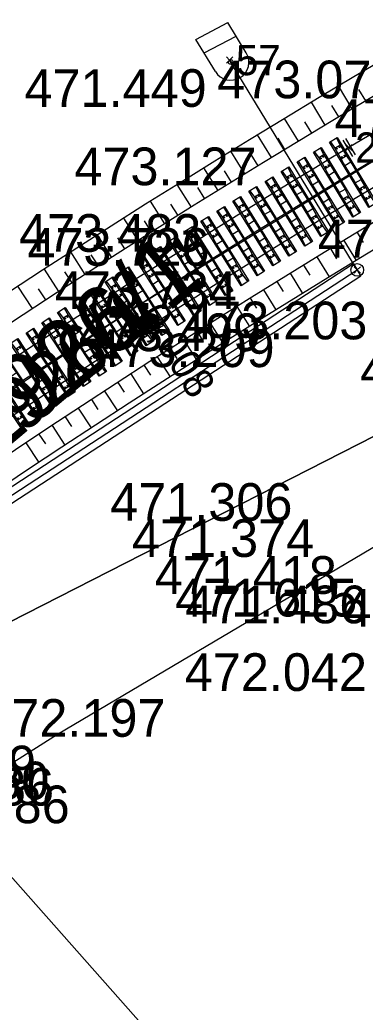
# Model space of a CAD drawing. Extents: x -758836 to -757729, y -1175316 to -1174366.
# Drawn here: x -758366.97 to -758355.97, y -1174833.52 to -1174801.92 of the extents above; entities that cross this region are included whole.
import ezdxf

# ---------------------------------------------------------------- set-up
doc = ezdxf.new("R2010")
doc.units = 0
for name, color, linetype in [('_NOR-body-stávající osa', 7, 'Continuous'), ('_NOR-návrh silná', 7, 'Continuous'), ('_NOR-návrh tenká', 7, 'Continuous'), ('_NOR-osa', 7, 'Continuous'), ('_NOR-posuny', 7, 'Continuous'), ('_NOR-pražce', 7, 'Continuous'), ('_NOR-svahy', 7, 'Continuous'), ('_vytyčený bod', 7, 'Continuous'), ('G_Obvod stavby', 7, 'Continuous'), ('Hranice parcel', 7, 'Continuous'), ('Parcelní čísla', 7, 'Continuous'), ('Vnitřní kresba', 7, 'Continuous'), ('Vrstva 1', 7, 'Continuous'), ('Vrstva 61', 7, 'Continuous')]:
    doc.layers.add(name, color=color, linetype=linetype)

# ---------------------------------------------------------------- blocks, each defined once
blk = doc.blocks.new('půdorys-SB8')
at = {"layer": '_NOR-pražce'}
for p, q in [((-1.21, 0.109), (-0.96, 0.095)), ((-0.96, 0.095), (-0.56, 0.099)), ((-0.96, 0.095), (-0.96, -0.095)), ((-0.56, 0.099), (-0.32, 0.109)), ((-0.56, 0.099), (-0.56, -0.1)), ((-0.32, 0.109), (0.32, 0.109)), ((-0.32, 0.109), (-0.32, -0.11)), ((0.56, 0.099), (0.32, 0.109)), ((0.32, -0.11), (0.32, 0.109)), ((0.96, 0.095), (0.56, 0.099)), ((0.56, 0.099), (0.56, -0.1)), ((1.21, 0.109), (0.96, 0.095)), ((0.96, 0.095), (0.96, -0.095)), ((-1.21, -0.11), (-0.96, -0.095)), ((-0.96, -0.095), (-0.56, -0.1)), ((-0.56, -0.1), (-0.32, -0.11)), ((-0.32, -0.11), (0.32, -0.11)), ((0.56, -0.1), (0.32, -0.11)), ((0.96, -0.095), (0.56, -0.1)), ((1.21, -0.11), (0.96, -0.095))]:
    blk.add_line(p, q, dxfattribs=at)
blk.add_lwpolyline([(-1.21, 0.142), (1.21, 0.142), (1.21, -0.142), (-1.21, -0.142)], close=True, dxfattribs=at)
for centre in [(-0.916, 0.048), (-0.604, 0.048), (0.604, 0.048), (0.916, 0.048), (-0.916, -0.048), (-0.604, -0.048), (0.604, -0.048), (0.916, -0.048)]:
    blk.add_circle(centre, 0.015, dxfattribs=at)
blk = doc.blocks.new('POINT_DISPLAY')
for p, q in [((-0.175, -0.175), (0.175, 0.175)), ((-0.175, 0.175), (0.175, -0.175))]:
    blk.add_line(p, q)

msp = doc.modelspace()

# ---------------------------------------------------------------- linework, layer by layer
at = {"layer": '_NOR-návrh silná'}
for p, q in [((-758356.686, -1174805.753), (-758356.377, -1174806.268)), ((-758356.6, -1174805.702), (-758356.291, -1174806.216))]:
    msp.add_line(p, q, dxfattribs=at)
at = {"layer": '_NOR-návrh tenká'}
for p, q in [((-758361.359, -1174802.548), (-758360.342, -1174802.008)), ((-758359.758, -1174802.968), (-758360.342, -1174802.008)), ((-758360.74, -1174803.566), (-758361.359, -1174802.548)), ((-758361.099, -1174802.976), (-758360.082, -1174802.436)), ((-758356.223, -1174809.884), (-758360.288, -1174803.203)), ((-758356.34, -1174809.692), (-758371.395, -1174819.503)), ((-758356.34, -1174809.692), (-758356.106, -1174810.077)), ((-758371.266, -1174819.688), (-758356.223, -1174809.884)), ((-758356.106, -1174810.077), (-758371.14, -1174819.874))]:
    msp.add_line(p, q, dxfattribs=at)
for centre, radius in [((-758360.249, -1174803.267), 0.075), ((-758356.223, -1174809.884), 0.2)]:
    msp.add_circle(centre, radius, dxfattribs=at)
for centre, radius, start, end in [((-758205.34, -1175057.864), 295.6, 97.09776, 129.28488), ((-758205.34, -1175057.864), 294.75, 97.0979, 129.28474), ((-758205.34, -1175057.864), 293.75, 97.09807, 120.96729), ((-758205.34, -1175057.864), 291.3, 97.09848, 129.28417), ((-758205.34, -1175057.864), 290.55, 97.09861, 129.28404), ((-758360.249, -1174803.267), 0.575, 211.3183, 31.3183), ((-758205.34, -1175057.864), 293.75, 120.96729, 129.28457), ((-758205.34, -1175057.864), 292.25, 120.96729, 129.28432)]:
    msp.add_arc(centre, radius, start, end, dxfattribs=at)
at = {"layer": '_NOR-osa'}
msp.add_arc((-758205.34, -1175057.864), 293, 97.09819, 129.28445, dxfattribs=at)
at = {"layer": '_NOR-svahy'}
for points in [[(-758356.383, -1174804.756), (-758356.819, -1174804.027)], [(-758355.954, -1174804.501), (-758356.171, -1174804.135)], [(-758357.241, -1174805.27), (-758357.679, -1174804.542)], [(-758356.812, -1174805.013), (-758357.031, -1174804.648)], [(-758358.097, -1174805.787), (-758358.538, -1174805.06)], [(-758357.669, -1174805.528), (-758357.889, -1174805.165)], [(-758358.952, -1174806.307), (-758359.395, -1174805.581)], [(-758358.525, -1174806.047), (-758358.745, -1174805.684)], [(-758359.804, -1174806.829), (-758360.25, -1174806.106)], [(-758359.378, -1174806.568), (-758359.6, -1174806.205)], [(-758360.655, -1174807.355), (-758361.103, -1174806.633)], [(-758360.23, -1174807.092), (-758360.453, -1174806.73)], [(-758361.504, -1174807.883), (-758361.954, -1174807.162)], [(-758361.08, -1174807.619), (-758361.304, -1174807.258)], [(-758362.351, -1174808.415), (-758362.804, -1174807.695)], [(-758361.928, -1174808.149), (-758362.154, -1174807.789)], [(-758363.197, -1174808.949), (-758363.652, -1174808.231)], [(-758362.774, -1174808.681), (-758363.001, -1174808.322)], [(-758364.04, -1174809.486), (-758364.498, -1174808.769)], [(-758363.619, -1174809.217), (-758363.847, -1174808.858)], [(-758356.225, -1174808.687), (-758356.031, -1174809.008)], [(-758357.08, -1174809.206), (-758356.884, -1174809.526)], [(-758356.653, -1174808.946), (-758356.263, -1174809.587)], [(-758364.882, -1174810.026), (-758365.342, -1174809.311)], [(-758364.461, -1174809.755), (-758364.691, -1174809.398)], [(-758357.506, -1174809.467), (-758357.114, -1174810.107)], [(-758365.722, -1174810.568), (-758366.184, -1174809.855)], [(-758357.932, -1174809.729), (-758357.736, -1174810.048)], [(-758365.302, -1174810.297), (-758365.533, -1174809.94)], [(-758358.358, -1174809.991), (-758357.964, -1174810.629)], [(-758366.56, -1174811.114), (-758367.025, -1174810.402)], [(-758366.141, -1174810.841), (-758366.373, -1174810.485)], [(-758358.783, -1174810.254), (-758358.586, -1174810.573)], [(-758359.632, -1174810.782), (-758359.434, -1174811.1)], [(-758359.208, -1174810.518), (-758358.812, -1174811.154)], [(-758360.056, -1174811.047), (-758359.658, -1174811.683)], [(-758360.48, -1174811.313), (-758360.28, -1174811.631)], [(-758360.903, -1174811.58), (-758360.502, -1174812.214)], [(-758361.325, -1174811.847), (-758361.124, -1174812.164)], [(-758362.169, -1174812.384), (-758361.967, -1174812.7)], [(-758361.747, -1174812.115), (-758361.345, -1174812.748)], [(-758362.59, -1174812.654), (-758362.185, -1174813.285)], [(-758363.011, -1174812.924), (-758362.808, -1174813.239)], [(-758363.431, -1174813.195), (-758363.024, -1174813.825)], [(-758363.85, -1174813.467), (-758363.646, -1174813.781)], [(-758364.27, -1174813.739), (-758363.861, -1174814.368)], [(-758365.107, -1174814.286), (-758364.696, -1174814.913)], [(-758364.689, -1174814.012), (-758364.483, -1174814.326)], [(-758365.525, -1174814.561), (-758365.319, -1174814.874)], [(-758365.942, -1174814.836), (-758365.529, -1174815.462)], [(-758366.359, -1174815.112), (-758366.152, -1174815.425)], [(-758366.775, -1174815.389), (-758366.36, -1174816.013)]]:
    msp.add_lwpolyline(points, dxfattribs=at)
at = {"layer": '_vytyčený bod'}
for p, q in [((-758360.288, -1174803.203), (-758360.388, -1174803.103)), ((-758360.288, -1174803.203), (-758360.388, -1174803.303)), ((-758360.288, -1174803.203), (-758360.188, -1174803.103)), ((-758360.288, -1174803.203), (-758360.188, -1174803.303)), ((-758356.489, -1174805.985), (-758356.589, -1174805.885)), ((-758356.489, -1174805.985), (-758356.589, -1174806.085)), ((-758356.489, -1174805.985), (-758356.389, -1174805.885)), ((-758356.489, -1174805.985), (-758356.389, -1174806.085)), ((-758356.223, -1174809.884), (-758356.323, -1174809.784)), ((-758356.223, -1174809.884), (-758356.123, -1174809.784)), ((-758356.223, -1174809.884), (-758356.323, -1174809.984)), ((-758356.223, -1174809.884), (-758356.123, -1174809.984))]:
    msp.add_line(p, q, dxfattribs=at)
at = {"layer": 'G_Obvod stavby'}
msp.add_lwpolyline([(-758392.72, -1174840.756), (-758391.23, -1174838.56), (-758368.37, -1174821.64), (-758340.31, -1174807.33), (-758320.27, -1174796.89), (-758301, -1174790.21), (-758267.96, -1174782.93), (-758224.96, -1174775.27), (-758184.87, -1174772.83), (-758142.71, -1174770.26), (-758089.84, -1174768.68), (-758106.02, -1174731.44), (-758149.09, -1174725.67), (-758199.62, -1174726.6), (-758225.76, -1174732.36), (-758252.17, -1174738.18), (-758254.97, -1174739.34), (-758266.58, -1174744.16), (-758279.45, -1174749.49), (-758302.42, -1174759.02), (-758331.68, -1174770.24), (-758367.17, -1174799.81), (-758405.64, -1174832.2)], dxfattribs=at)
at = {"layer": 'Hranice parcel'}
for points in [[(-758340.31, -1174807.33), (-758368.37, -1174821.64), (-758391.23, -1174838.56)], [(-758352.89, -1174817.05), (-758365.77, -1174824.68), (-758369.29, -1174826.9), (-758373.7, -1174830.81), (-758376.95, -1174833.7), (-758377.89, -1174834.53), (-758384.91, -1174840.91)]]:
    msp.add_lwpolyline(points, dxfattribs=at)
at = {"layer": 'Vnitřní kresba'}
msp.add_line((-758369.29, -1174826.9), (-758358.97, -1174838.54), dxfattribs=at)
at = {"layer": 'Vrstva 1'}
msp.add_lwpolyline([(-758443.817, -1174881.252), (-758441.673, -1174879.1), (-758423.412, -1174860.854), (-758412.446, -1174850.23), (-758405.322, -1174843.614), (-758399.028, -1174837.996), (-758392.64, -1174832.554), (-758380.106, -1174822.693), (-758371.773, -1174816.721), (-758363.37, -1174811.125), (-758354.46, -1174805.649), (-758345.526, -1174800.592), (-758336.614, -1174795.909), (-758327.338, -1174791.462), (-758317.813, -1174787.314), (-758307.666, -1174783.315), (-758298.059, -1174779.921), (-758285.017, -1174775.914), (-758275.047, -1174773.289)], dxfattribs=at)

# ---------------------------------------------------------------- block references
at = {"layer": '_NOR-body-stávající osa'}
msp.add_blockref('POINT_DISPLAY', (-758363.37, -1174811.125), dxfattribs=at)
at = {"layer": '_NOR-pražce'}
for p, rotation in [((-758356.359, -1174806.782), -58.974233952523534), ((-758356.872, -1174807.091), -58.85720429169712), ((-758357.383, -1174807.401), -58.74017459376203), ((-758357.895, -1174807.712), -58.623144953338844), ((-758358.405, -1174808.024), -58.506115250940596), ((-758358.915, -1174808.337), -58.38908558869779), ((-758359.425, -1174808.652), -58.27205592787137), ((-758359.933, -1174808.967), -58.155026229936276), ((-758360.441, -1174809.283), -58.03799658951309), ((-758360.949, -1174809.6), -57.920966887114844), ((-758361.456, -1174809.919), -57.80393722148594), ((-758361.962, -1174810.238), -57.6869075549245), ((-758362.467, -1174810.559), -57.56987785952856), ((-758362.972, -1174810.88), -57.45284819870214), ((-758363.476, -1174811.203), -57.33581850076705), ((-758363.98, -1174811.526), -57.218788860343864), ((-758364.483, -1174811.851), -57.101759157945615), ((-758364.985, -1174812.176), -56.98472949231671), ((-758365.486, -1174812.503), -56.86769982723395), ((-758365.987, -1174812.83), -56.75067012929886), ((-758366.487, -1174813.159), -56.63364048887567), ((-758366.987, -1174813.489), -56.51661078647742), ((-758367.485, -1174813.819), -56.399581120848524)]:
    msp.add_blockref('půdorys-SB8', p, dxfattribs=dict(at, rotation=rotation))

# ---------------------------------------------------------------- texts
at = {"layer": '_NOR-posuny'}
msp.add_text('0,008', height=0.9599, rotation=302.6385, dxfattribs=at).set_placement((-758363.231, -1174811.342))
at = {"layer": '_vytyčený bod'}
for s, height, p in [('57', 0.9599, (-758360.088, -1174803.683)), ('57', 0.9596, (-758360.088, -1174803.683)), ('24', 0.9599, (-758356.289, -1174806.465)), ('24', 0.9596, (-758356.289, -1174806.465))]:
    msp.add_text(s, height=height, dxfattribs=at).set_placement(p)
at = {"layer": 'Parcelní čísla'}
for height in [2.1751, 1.7]:
    msp.add_text('2926/1', height=height, rotation=40, dxfattribs=at).set_placement((-758367.845, -1174815.948))
at = {"layer": 'Vrstva 61'}
for s, p in [('473.071', (-758360.68, -1174804.418)), ('471.449', (-758366.817, -1174804.692)), ('473.628', (-758356.945, -1174805.649)), ('473.127', (-758365.23, -1174807.186)), ('473.483', (-758366.991, -1174809.307)), ('473.157', (-758357.48, -1174809.488)), ('473.726', (-758366.727, -1174809.753)), ('473.734', (-758365.855, -1174811.125)), ('473.203', (-758361.702, -1174812.093)), ('473.499', (-758365.087, -1174812.469)), ('473.209', (-758364.656, -1174812.977)), ('470.401', (-758356.128, -1174813.67)), ('471.306', (-758364.088, -1174817.872)), ('471.374', (-758363.395, -1174819.023)), ('471.418', (-758362.671, -1174820.197)), ('471.615', (-758362.023, -1174820.919)), ('471.486', (-758361.704, -1174821.135)), ('470.648', (-758356.658, -1174821.242)), ('472.042', (-758361.714, -1174823.289)), ('472.197', (-758368.13, -1174824.749)), ('472.459', (-758372.247, -1174826.232)), ('472.380', (-758371.829, -1174826.741)), ('472.386', (-758371.677, -1174826.94)), ('472.386', (-758371.179, -1174827.501))]:
    msp.add_text(s, height=1.2, dxfattribs=at).set_placement(p)

doc.saveas('drawing.dxf')
